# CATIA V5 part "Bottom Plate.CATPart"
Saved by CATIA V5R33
Part number: Bottom Plate
Bounding box of the stored display mesh (mm): x -125 to 125, y 0 to 150, z 0 to 30
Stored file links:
  D:\PROJECTS\Project 2023\CATIA V5 6R 2023\Resources\Tutorial Files\c12_catia_v5_6r2023_tut\c12tut2\Bottom Plate.CATPart
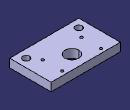
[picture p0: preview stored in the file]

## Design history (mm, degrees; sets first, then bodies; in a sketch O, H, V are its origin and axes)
Body1 (main body)
  Sketch1 on xy-plane, origin (0, 0, 0), H (1, 0, 0), V (0, 1, 0)
    point P1 (-125, 0)
    line L1 (-125, 0) -> (125, 0)
    line L2 (125, 0) -> (125, 150)
    line L3 (125, 150) -> (-125, 150)
    line L4 (-125, 150) -> (-125, 0)
    circle A1 centre (0, 100) radius 25
    point P5 (0, 100)
    circle A2 centre (95, 30) radius 12.5
    point P6 (95, 30)
    circle A3 centre (-95, 30) radius 12.5
    circle A4 centre (-70, 135) radius 5
    point P8 (-70, 135)
    construction line L5 (-25, 100) -> (25, 100)
    point P9 (-25, 100)
    point P10 (25, 100)
    construction line L6 (0, 125) -> (0, 75)
    point P11 (0, 125)
    point P12 (0, 75)
    circle A5 centre (-70, 65) radius 5
    circle A6 centre (70, 135) radius 5
    circle A7 centre (70, 65) radius 5
    length L1 = 250
    length L2 = 150
    radius A1 = 25
    distance P5 L1 = 100
    distance P6 L2 = 30
    distance L1 P6 = 30
    radius A2 = 12.5
    distance P5 P8 V = 35
    distance P5 P8 H = 70
    radius A4 = 5
    distance L1 L5 = 100
    coincidence: P1 H, P5 V, P9 A1, P10 A1, P11 A1, P11 V, P12 A1
    horizontal: L1 H, L3 H, L5 H
    vertical: L2 V, L4 V, L6 V
    symmetry: L4 L2 V, A2 A3 V, A4 A5 L5, A4 A6 L6, A5 A7 L6
  Pad1: profile Sketch1, direction (0, 0, 1), length 30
